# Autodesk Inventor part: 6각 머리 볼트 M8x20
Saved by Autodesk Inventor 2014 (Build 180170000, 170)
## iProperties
Created: 2026-04
Part Number: 6각 머리 볼트 M8x20
Material: 강철, 연강
Document SubType Name: Modeling
Designer: dg
Density: 7.86 g/cm^3
Appearance: 강철
Mass: 13.7364 g
Surface Area: 10.1004 cm^2
Volume: 1.74764 cm^3
Author: jhkim
Description: 6각 머리 볼트 및 6각 머리 나사
Creation Date: 2026-03-27
Sending System: Autodesk Inventor 2026
Preprocessor: ST-DEVELOPER v20.1
Author: dg
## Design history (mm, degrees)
node "6각 머리 볼트 M8x201"
body "Solid1"
node "기준1"
